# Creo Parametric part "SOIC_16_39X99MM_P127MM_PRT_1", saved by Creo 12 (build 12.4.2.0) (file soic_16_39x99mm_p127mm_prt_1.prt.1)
Units: Custom; MM, KILOGRAM, SECS

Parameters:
  PTC_WM_ITERATION = "0"
  PTC_WM_VERSION = "-.0"
  PTC_WM_LIFECYCLE_STATE = "In Work"
  PTC_WM_LIFECYCLE = "MO_CADDocument"
  PTC_WM_CREATED_BY = "Maximilian Roepper (Z0017RMS: MO)"
  PTC_WM_CREATED_ON = "18-Sep-26 11:36:42 AM"
  PTC_WM_MODIFIED_BY = "Maximilian Roepper (Z0017RMS: MO)"
  PTC_WM_MODIFIED_ON = "18-Sep-26 11:36:46 AM"
  PDMLINKNUMBER = "PDM000071455227"
  PTC_WM_NAME = "soic_16_39x99mm_p127mm_prt_1.prt"
  PTC_WM_NUMBER = "PDM000071455227"

Other parameters: WEIGHT, WEIGHT_FACTOR, WEIGHT_ADD, _MASS_TEMP, _DIFF_TEMP, MC_ERRORS, SUPPLIER

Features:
  1. coordinate system
  2. datum plane "PRT_YZ"
  3. datum plane "PRT_XY"
  4. datum plane "PRT_XZ"
  5. coordinate system
  6. datum axis
  7. datum axis
  8. datum axis
  9. coordinate system
  10. imported feature
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
Other named items: PRT, SIEMENS_MO, DRW_VIEW_ORG, PRT_X, PRT_Y, PRT_Z, CS0, ROUGH_GROB

Layers: 00_STD_CSYS-KSYS, 01_STD_PLANES-EBENEN, 02_STD_AXES-ACHSEN, 03_STD_CSYS-KSYS, 24_IMPORT_FEAT-IMPORT_KE

Surfaces: 211 plane, 66 cylinder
